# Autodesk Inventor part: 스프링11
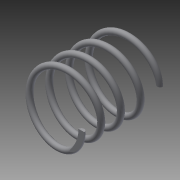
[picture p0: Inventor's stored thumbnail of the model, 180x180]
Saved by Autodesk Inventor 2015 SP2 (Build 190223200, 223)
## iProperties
Created: 2015-06
Part Number: 스프링11
Material: 일반
Document SubType Name: Modeling
Designer: AMC
Density: 1 g/cm^3
Appearance: 기본값
Mass: 0.349967 g
Surface Area: 9.47047 cm^2
Volume: 0.349967 cm^3
Author: AMC
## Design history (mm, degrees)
sketch "스케치1"
  geometry: L1 (0, 0)-(8, 0); L2 (8, 0)-(8, 20.5); L3 (8, 20.5)-(0, 20.5); L4 (0, 20.5)-(0, 0); C1 r 0.75 at (8, 0)
  constraints: 8 end point, 2 parallel, 1 centre point, 1 coincident, 1 horizontal, 1 perpendicular
  dimensions: "d0" = 8 distance of L3.end L2.end; "d3" = 1.5 diameter of C1; "d15" = 20.5 distance of L1.end L2.end (derived); "d16" = 20.5 distance between parallel lines of L1 L3 (derived)
feature "코일1" sketch "스케치1" pitch "d4" = 10; turns "d6" = 4; dims "d5" = 20.5 (= d15), "d7" = 0, angle "d8" = 90 deg, angle "d9" = 90 deg, "d10" = 0, "d11" = 0
sketch "스케치2"
  geometry: L1 (2.971, 0)-(-21.019, 0); L2 (-21.019, 0)-(-21.019, -29.714); L3 (-21.019, -29.714)-(2.971, -29.714); L4 (2.971, -29.714)-(2.971, 0); L5 (4.181, 20.5)-(-23.875, 20.5); L6 (-23.875, 20.5)-(-23.875, 52.277); L7 (-23.875, 52.277)-(4.181, 52.277); L8 (4.181, 52.277)-(4.181, 20.5); C1 r 0.75 at (0, 0) reference; C2 r 0.75 at (0, 20.5) reference; 8 further points
  constraints: 16 end point, 4 parallel, 2 horizontal, 2 perpendicular, 1 point on line, 7 other
  dimensions: "d12" = 20.5 distance between parallel lines of L1 L5 (= d15)
extrude "돌출1" cut sketch "스케치2" stored distance "d13" = 123; taper "d14" = 0 deg
node "솔리드1"
node "절단 모서리 투영1"
other parameters: "d1" = 10.5 (derived)
